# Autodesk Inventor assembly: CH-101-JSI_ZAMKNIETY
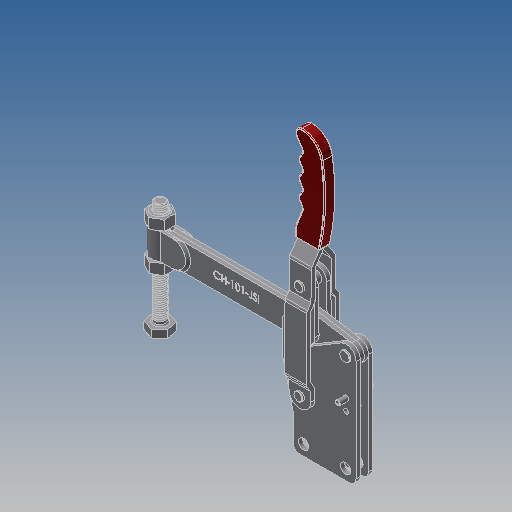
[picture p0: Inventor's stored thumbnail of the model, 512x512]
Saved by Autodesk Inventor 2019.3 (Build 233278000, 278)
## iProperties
Company: Î¢ÈíÖÐ¹ú
Created: 2012-09
Part Number: CH-101-JSI_ZAMKNIETY
Material: Ogólny
Description: STEP AP203
Document SubType Name: Assembly
Designer: CADENGINEERING4
Sending System: SolidWorks 2010
Preprocessor: SwSTEP 2.0
Title: CH-101-JSI.STEP
Author: Î¢ÈíÓÃ»§
Revision Number: ÈÎºÎ
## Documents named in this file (14)
- E:\STRONA\Piotrek\CH-101-JSI\CH-101-JSI_ZAMKNIETY.iam
- E:\STRONA\Piotrek\CH-101-JSI\CH-101-JSI-02 SOLID BAR_Ä¬ÈÏ_°´¼Ó¹¤_.ipt
- E:\STRONA\Piotrek\CH-101-JSI\CH-101-J-11.ipt
- E:\STRONA\Piotrek\CH-101-JSI\CH-10247-09.ipt
- E:\STRONA\Piotrek\CH-101-JSI\CH-101-J-03 HANDLE.ipt
- E:\STRONA\Piotrek\CH-101-JSI\CH-10247-08.ipt
- E:\STRONA\Piotrek\CH-101-JSI\CH-101-JSB-01 STRAIGHT BASE.ipt
- E:\STRONA\Piotrek\CH-101-JSI\3-8-16 LOCK NUT.ipt
- E:\STRONA\Piotrek\CH-101-JSI\CH-101-J-06.ipt
- E:\STRONA\Piotrek\CH-101-JSI\CH-101-J-07.ipt
- E:\STRONA\Piotrek\CH-101-JSI\CH-10247-05.ipt
- E:\STRONA\Piotrek\CH-101-JSI\CH-101-J-04 CONNECTING-PLATE.ipt
- E:\STRONA\Piotrek\CH-101-JSI\CH-SA-58500 NUT.ipt
- E:\STRONA\Piotrek\CH-101-JSI\CH-SA-58500 SPINDLE SUPPLIED.ipt
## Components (18 placed, 18 different names)
1. CH-101-JSI-02 SOLID BAR_Ä¬ÈÏ<°´¼Ó¹¤>_1
2. CH-101-J-11_2
3. CH-10247-09_3
4. CH-101-J-03 HANDLE_4
5. CH-10247-08_5
6. CH-101-JSB-01 STRAIGHT BASE_6
7. CH-101-J-11_7
8. 3-8-16 LOCK NUT_8
9. CH-101-J-06_9
10. CH-101-J-06_10
11. CH-101-J-07_11
12. CH-10247-05_12
13. CH-101-J-04 CONNECTING-PLATE_13
14. 3-8-16 LOCK NUT_14
15. CH-SA-58500 NUT_15
16. CH-SA-58500 SPINDLE SUPPLIED_16
17. CH-10247-08_17
18. CH-SA-58500 NUT_18
